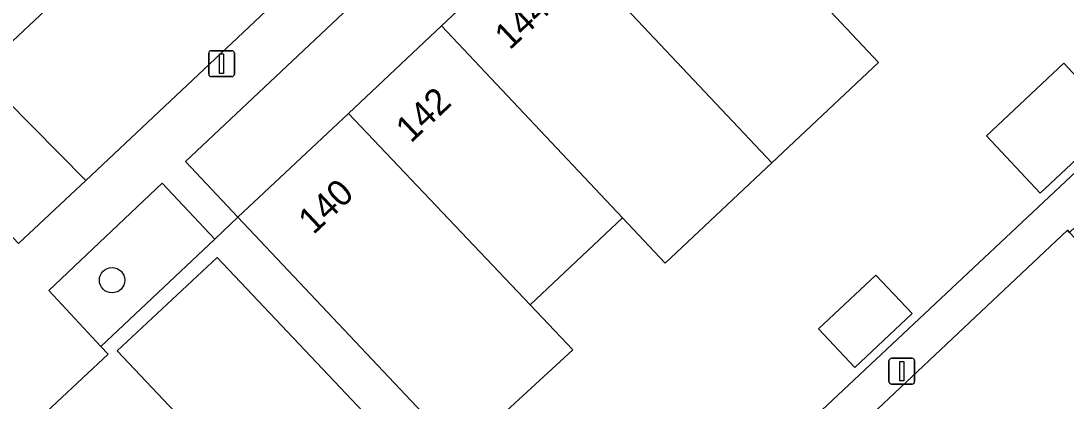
# Model space of a CAD drawing. Extents: x 162542 to 163147, y 380779 to 381521.
# Drawn here: x 162800.39 to 162840.71, y 381347.2 to 381361.88 of the extents above; entities that cross this region are included whole.
import ezdxf

# ---------------------------------------------------------------- set-up
doc = ezdxf.new("R2010")
doc.units = 0
for name, color, linetype in [('IMGEO_Boom', 7, 'Continuous'), ('IMGEO_Erf', 7, 'Continuous'), ('IMGEO_Groenvoorziening', 7, 'Continuous'), ('IMGEO_Lichtmast', 7, 'Continuous'), ('IMGEO_Pand', 7, 'Continuous'), ('IMGEO_Pand_nummerreeks', 7, 'Continuous'), ('IMGEO_Parkeervlak_open', 7, 'Continuous'), ('IMGEO_Rijbaan_lokaal_open', 7, 'Continuous'), ('IMGEO_Voetpad_open', 7, 'Continuous')]:
    doc.layers.add(name, color=color, linetype=linetype)

msp = doc.modelspace()

# ---------------------------------------------------------------- linework, layer by layer
at = {"layer": 'IMGEO_Boom'}
msp.add_circle((162803.909, 381351.872), 0.489, dxfattribs=at)
at = {"layer": 'IMGEO_Erf'}
for points in [[(162832.533, 381376.669), (162836.63, 381380.526), (162840.219, 381383.903), (162844.476, 381387.91), (162848.103, 381391.324), (162852.017, 381395.007), (162849.964, 381397.181), (162806.738, 381356.451), (162808.765, 381354.3), (162813.03, 381358.314), (162816.619, 381361.692), (162820.735, 381365.566), (162824.851, 381369.44), (162828.447, 381372.824)], [(162840.62, 381360.251), (162841.305, 381359.523), (162843.451, 381361.541), (162844.849, 381360.056), (162842.699, 381358.042), (162839.704, 381355.236), (162837.635, 381357.443)], [(162834.769, 381350.583), (162832.553, 381348.506), (162831.153, 381349.997), (162833.368, 381352.072)]]:
    msp.add_lwpolyline(points, close=True, dxfattribs=at)
msp.add_lwpolyline([(162831.83, 381362.028), (162833.474, 381360.282), (162829.361, 381356.408), (162825.248, 381352.534), (162823.601, 381354.282), (162820.037, 381350.925), (162821.684, 381349.188), (162817.344, 381345.198), (162823.189, 381339.252), (162824.174, 381340.177), (162851.755, 381366.101)], dxfattribs=at)
at = {"layer": 'IMGEO_Groenvoorziening'}
for points in [[(162819.386, 381371.27), (162815.416, 381375.559), (162798.77, 381359.886), (162802.891, 381355.725)], [(162798.77, 381359.886), (162796.271, 381357.534), (162796.7, 381357.097), (162800.306, 381353.289), (162802.891, 381355.725)], [(162807.869, 381353.455), (162805.845, 381355.623), (162801.468, 381351.477), (162803.476, 381349.313)]]:
    msp.add_lwpolyline(points, close=True, dxfattribs=at)
at = {"layer": 'IMGEO_Lichtmast'}
for p, q in [((162807.638, 381359.833), (162807.638, 381360.633)), ((162807.638, 381360.633), (162807.638, 381359.833)), ((162807.738, 381360.733), (162808.528, 381360.733)), ((162808.528, 381360.733), (162807.738, 381360.733)), ((162808.628, 381360.633), (162808.628, 381359.833)), ((162808.628, 381359.833), (162808.628, 381360.633)), ((162808.528, 381359.733), (162807.738, 381359.733)), ((162807.738, 381359.733), (162808.528, 381359.733)), ((162833.873, 381347.959), (162833.873, 381348.759)), ((162833.873, 381348.759), (162833.873, 381347.959)), ((162833.973, 381348.859), (162834.763, 381348.859)), ((162834.763, 381348.859), (162833.973, 381348.859)), ((162834.863, 381348.759), (162834.863, 381347.959)), ((162834.863, 381347.959), (162834.863, 381348.759)), ((162834.763, 381347.859), (162833.973, 381347.859)), ((162833.973, 381347.859), (162834.763, 381347.859))]:
    msp.add_line(p, q, dxfattribs=at)
for points in [[(162808.058, 381360.608), (162808.208, 381360.608), (162808.208, 381359.858), (162808.058, 381359.858), (162808.058, 381360.608)], [(162834.293, 381348.734), (162834.443, 381348.734), (162834.443, 381347.984), (162834.293, 381347.984), (162834.293, 381348.734)]]:
    msp.add_lwpolyline(points, dxfattribs=at)
for centre, start, end in [((162807.738, 381360.633), 90, 180), ((162807.738, 381360.633), 90, 180), ((162808.528, 381360.633), 0, 90), ((162808.528, 381360.633), 360, 90), ((162807.738, 381359.833), 180, 270), ((162807.738, 381359.833), 180, 270), ((162808.528, 381359.833), 270, 0), ((162808.528, 381359.833), 270, 0), ((162833.973, 381348.759), 90, 180), ((162833.973, 381348.759), 90, 180), ((162834.763, 381348.759), 0, 90), ((162834.763, 381348.759), 360, 90), ((162833.973, 381347.959), 180, 270), ((162833.973, 381347.959), 180, 270), ((162834.763, 381347.959), 270, 0), ((162834.763, 381347.959), 270, 0)]:
    msp.add_arc(centre, 0.1, start, end, dxfattribs=at)
at = {"layer": 'IMGEO_Pand'}
for points in [[(162824.851, 381369.44), (162820.735, 381365.566), (162829.361, 381356.408), (162833.474, 381360.282), (162831.83, 381362.028)], [(162820.735, 381365.566), (162816.619, 381361.692), (162823.601, 381354.282), (162825.248, 381352.534), (162829.361, 381356.408)], [(162816.619, 381361.692), (162813.03, 381358.314), (162820.037, 381350.925), (162823.601, 381354.282)], [(162841.305, 381359.523), (162840.62, 381360.251), (162837.635, 381357.443), (162839.704, 381355.236), (162842.699, 381358.042)], [(162813.03, 381358.314), (162808.765, 381354.3), (162817.167, 381345.386), (162817.344, 381345.198), (162821.684, 381349.188), (162820.037, 381350.925)], [(162833.368, 381352.072), (162831.153, 381349.997), (162832.553, 381348.506), (162834.769, 381350.583)]]:
    msp.add_lwpolyline(points, close=True, dxfattribs=at)
at = {"layer": 'IMGEO_Parkeervlak_open'}
for points in [[(162844.405, 381349.917), (162844.218, 381350.117), (162840.84, 381353.72), (162840.761, 381353.805), (162832.984, 381346.464), (162824.203, 381338.162), (162827.898, 381334.19)], [(162807.957, 381352.744), (162804.1, 381349.139), (162821.48, 381330.755), (162825.212, 381334.233), (162825.342, 381334.355)]]:
    msp.add_lwpolyline(points, close=True, dxfattribs=at)
at = {"layer": 'IMGEO_Rijbaan_lokaal_open'}
for points in [[(162756.449, 381320.051), (162778.553, 381340.869), (162779.523, 381341.782), (162789.16, 381350.859), (162791.871, 381353.412), (162796.271, 381357.534), (162798.77, 381359.886), (162815.416, 381375.559), (162816.39, 381376.475), (162830.414, 381389.679), (162826.908, 381393.237), (162824.8, 381391.23), (162823.097, 381389.628), (162814.669, 381381.699), (162813.221, 381380.336), (162801.582, 381369.385), (162800.131, 381368.02), (162782.534, 381351.464), (162781.079, 381350.096), (162772.455, 381341.982), (162771.017, 381340.629), (162766.646, 381336.517), (162765.201, 381335.157), (162756.116, 381326.609)], [(162831.614, 381329.7), (162831.86, 381329.93), (162827.898, 381334.19), (162824.203, 381338.162), (162823.189, 381339.252), (162822.899, 381338.98), (162816.878, 381345.112), (162817.167, 381345.386), (162808.765, 381354.3), (162807.869, 381353.455), (162803.476, 381349.313), (162803.752, 381349.015), (162799.802, 381345.305)], [(162804.1, 381349.139), (162807.957, 381352.744), (162825.342, 381334.355), (162825.212, 381334.233), (162826.296, 381333.075), (162822.97, 381329.945)], [(162822.237, 381329.955), (162821.48, 381330.755), (162804.1, 381349.139)]]:
    msp.add_lwpolyline(points, dxfattribs=at)
at = {"layer": 'IMGEO_Voetpad_open'}
for points in [[(162759.551, 381312.085), (162767.631, 381319.682), (162774.455, 381326.101), (162774.873, 381326.494), (162776.165, 381327.71), (162792.267, 381342.856), (162794.318, 381340.678), (162795.204, 381341.513), (162793.134, 381343.703), (162796.306, 381346.684), (162797.47, 381347.778), (162799.53, 381345.593), (162799.802, 381345.305), (162803.752, 381349.015), (162803.476, 381349.313), (162801.468, 381351.477), (162805.845, 381355.623), (162807.869, 381353.455), (162808.765, 381354.3), (162806.738, 381356.451), (162849.964, 381397.181)], [(162819.386, 381371.27), (162802.891, 381355.725), (162800.306, 381353.289), (162796.7, 381357.097), (162796.271, 381357.534), (162791.871, 381353.412), (162792.281, 381352.98), (162795.899, 381349.187), (162793.157, 381346.59), (162783.519, 381337.462), (162779.523, 381341.782), (162778.553, 381340.869), (162782.533, 381336.598), (162760.377, 381315.688)], [(162851.755, 381366.101), (162824.174, 381340.177), (162823.189, 381339.252), (162824.203, 381338.162), (162832.984, 381346.464), (162840.761, 381353.805), (162840.84, 381353.72), (162842.286, 381355.089), (162845.65, 381351.468), (162844.218, 381350.117), (162844.405, 381349.917), (162845.83, 381351.275), (162846.747, 381352.149), (162843.132, 381356.025), (162850.249, 381362.722)]]:
    msp.add_lwpolyline(points, dxfattribs=at)

# ---------------------------------------------------------------- texts
at = {"layer": 'IMGEO_Pand_nummerreeks'}
for s, p in [('144', (162819.246, 381360.731)), ('142', (162815.434, 381357.143)), ('140', (162811.674, 381353.605))]:
    msp.add_text(s, height=1, rotation=43.264, dxfattribs=at).set_placement(p)

doc.saveas('drawing.dxf')
